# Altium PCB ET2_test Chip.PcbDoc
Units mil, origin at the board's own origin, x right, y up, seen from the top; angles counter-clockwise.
Board outline 4000 x 3600 mil, 4 copper layers (Top Layer, GND, POWER, Bottom Layer), stack 61.6 mil thick; 148 components, 68 nets, 450 pads, 320 vias.
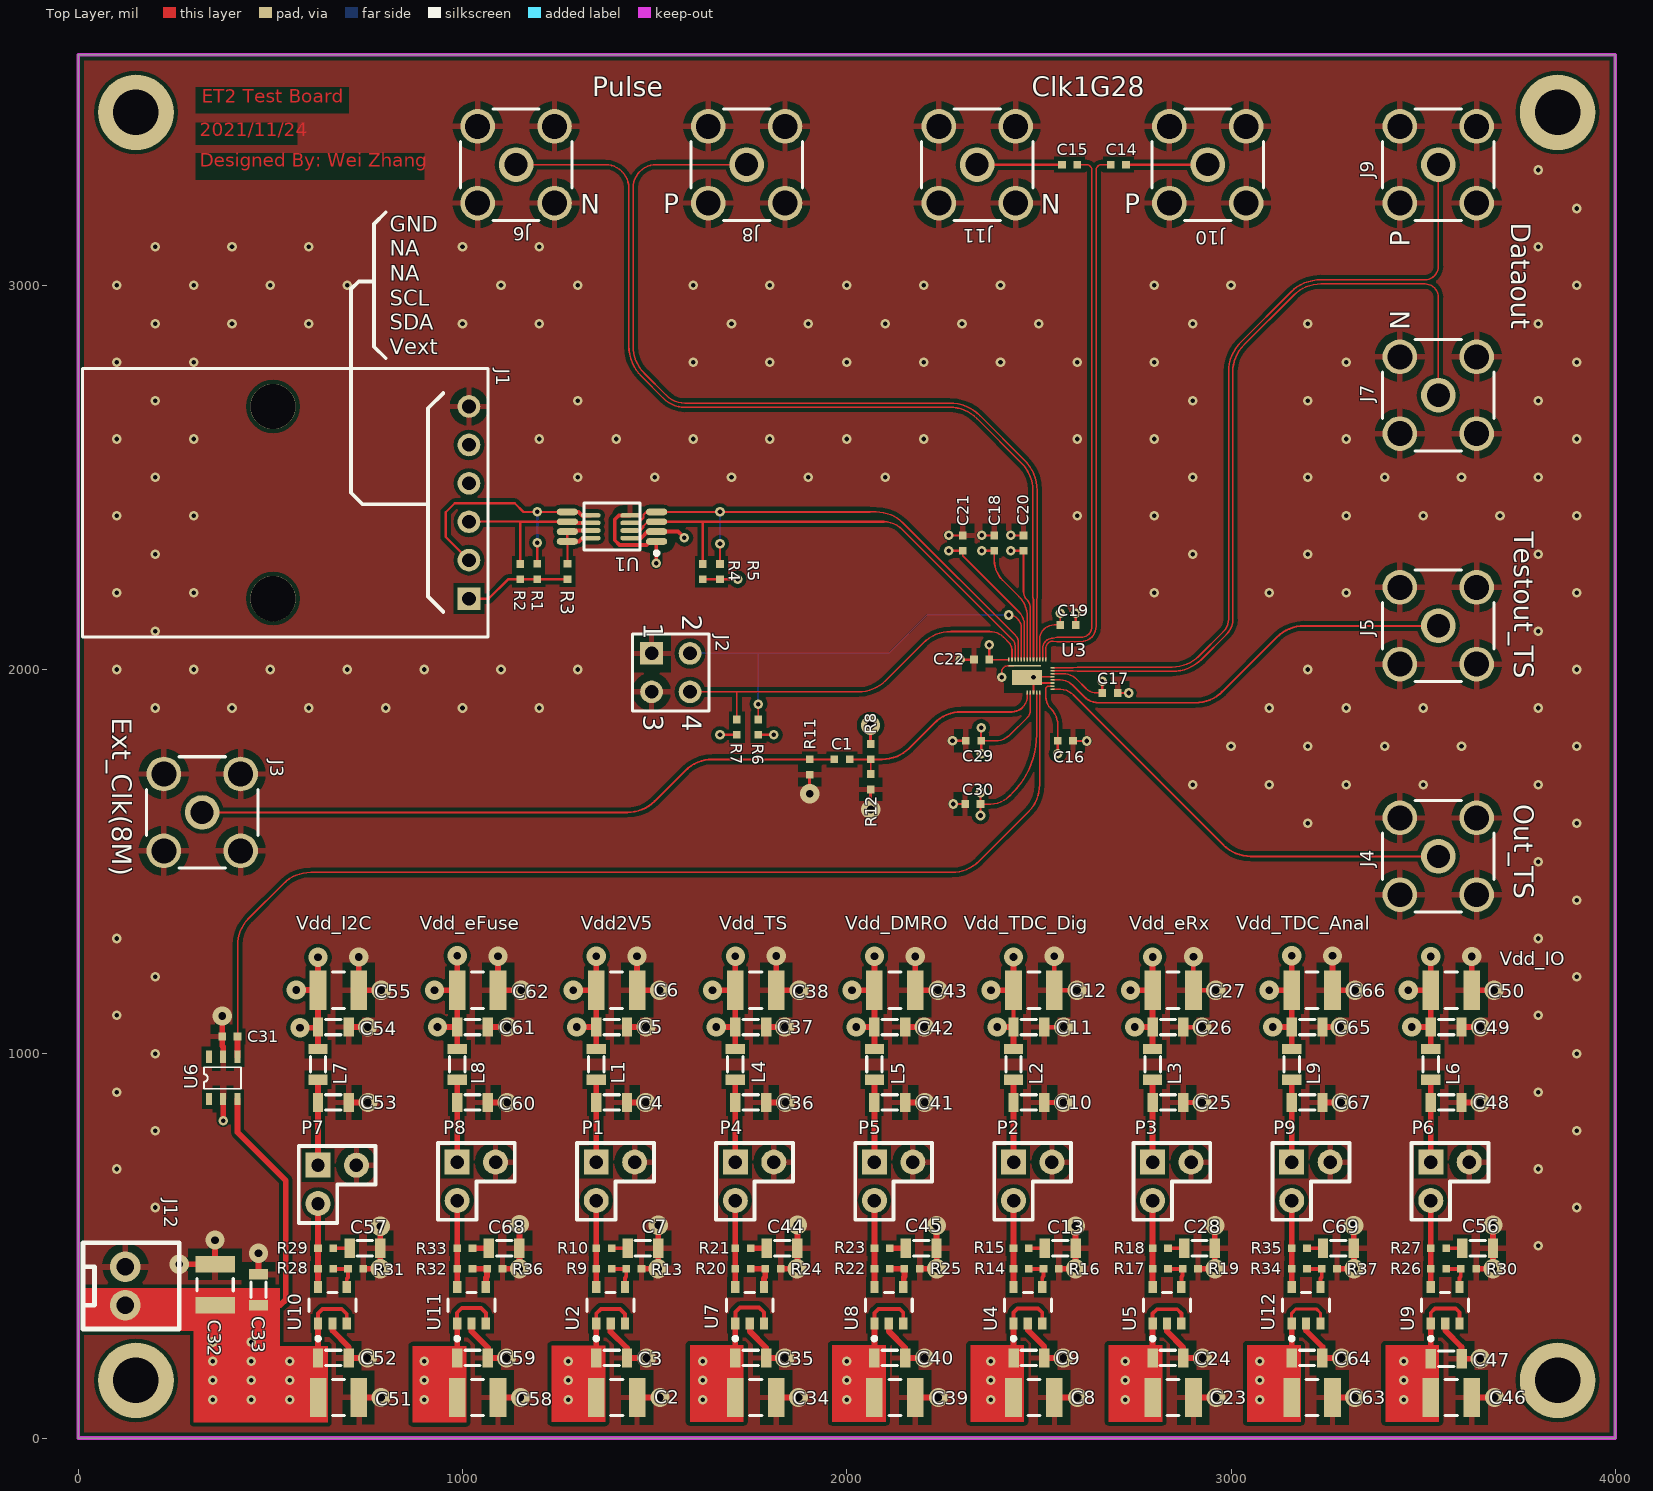
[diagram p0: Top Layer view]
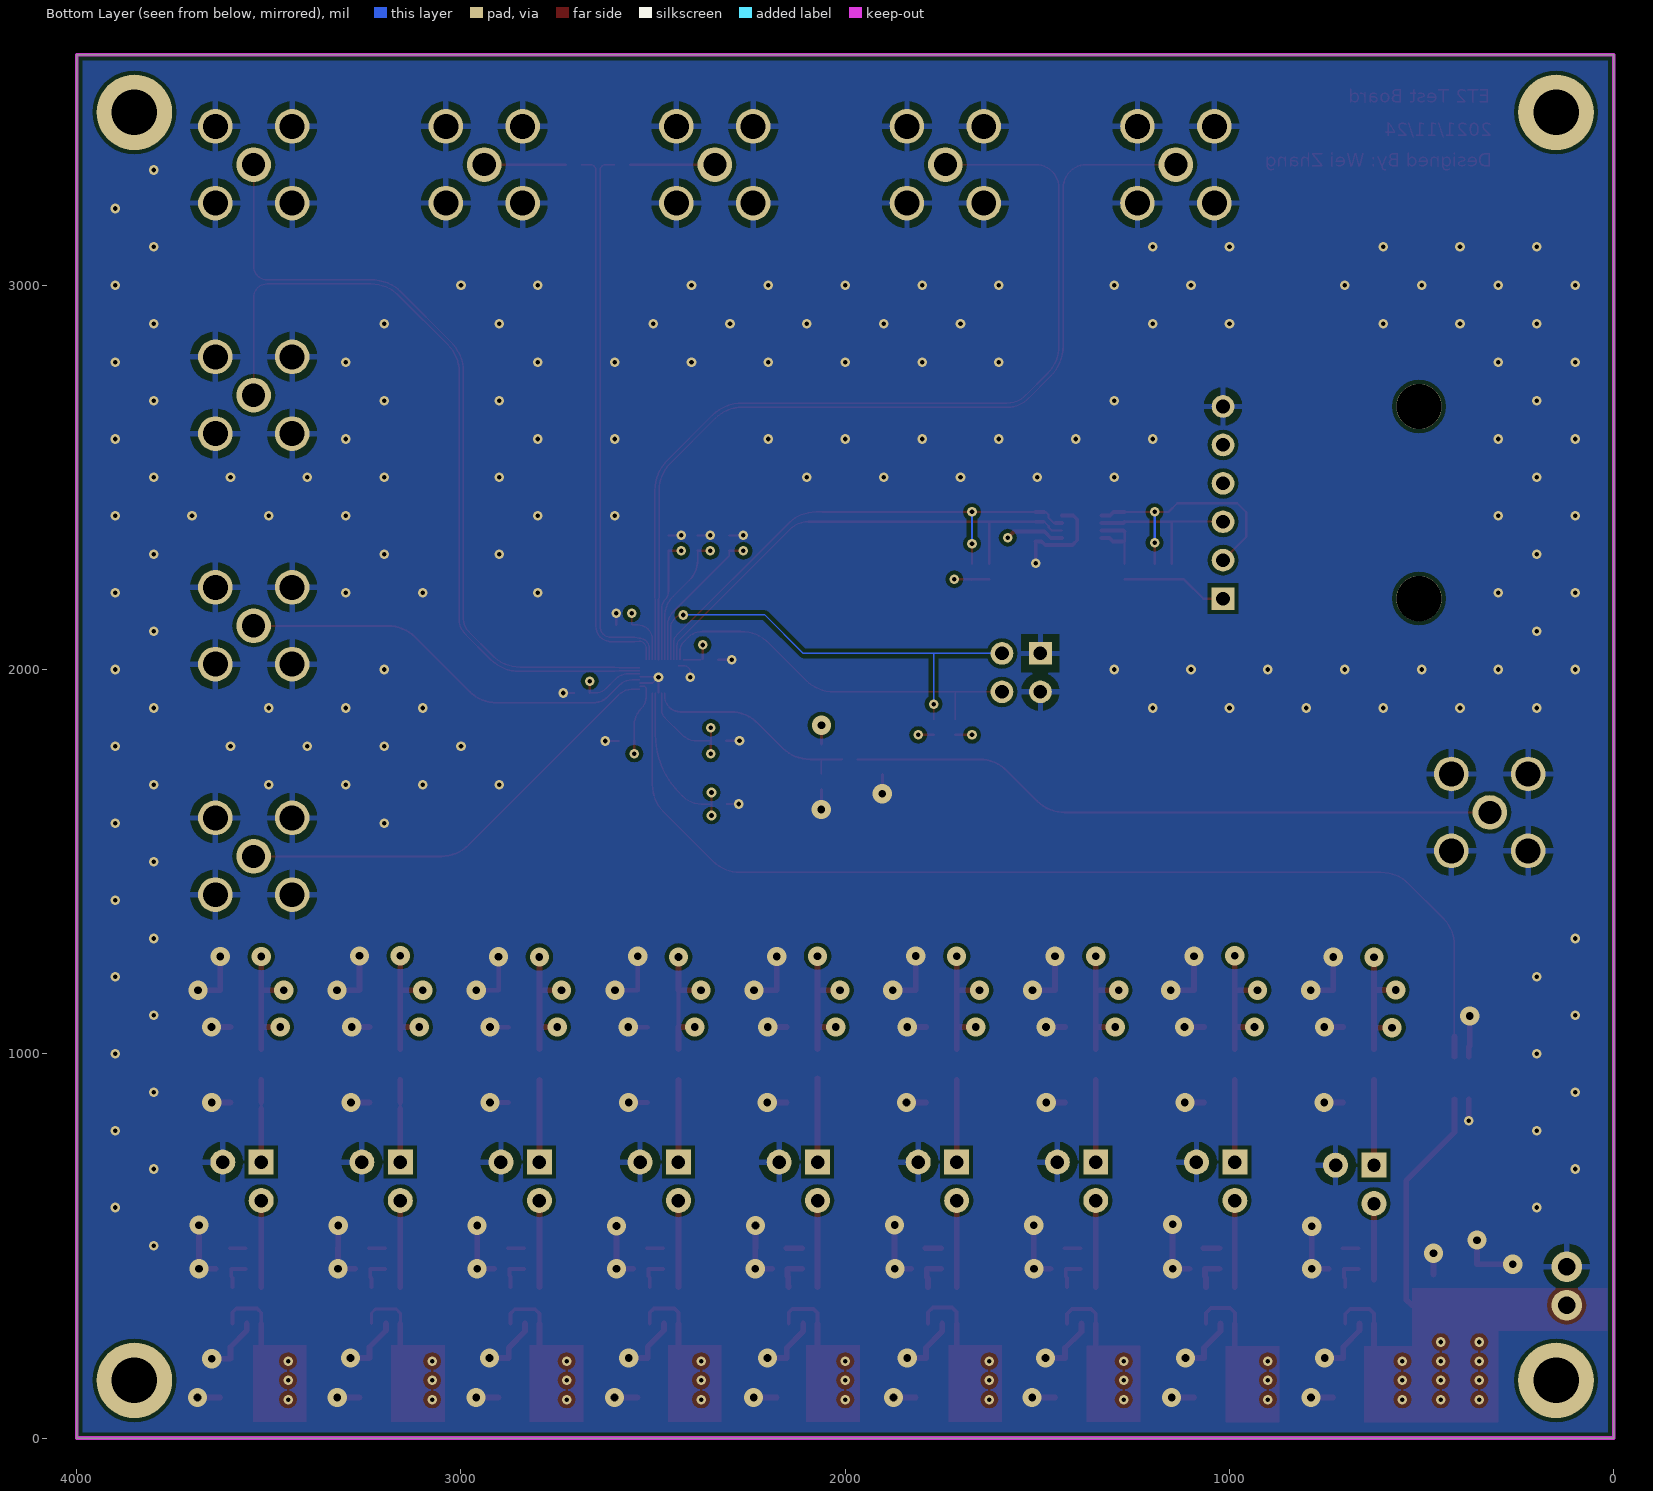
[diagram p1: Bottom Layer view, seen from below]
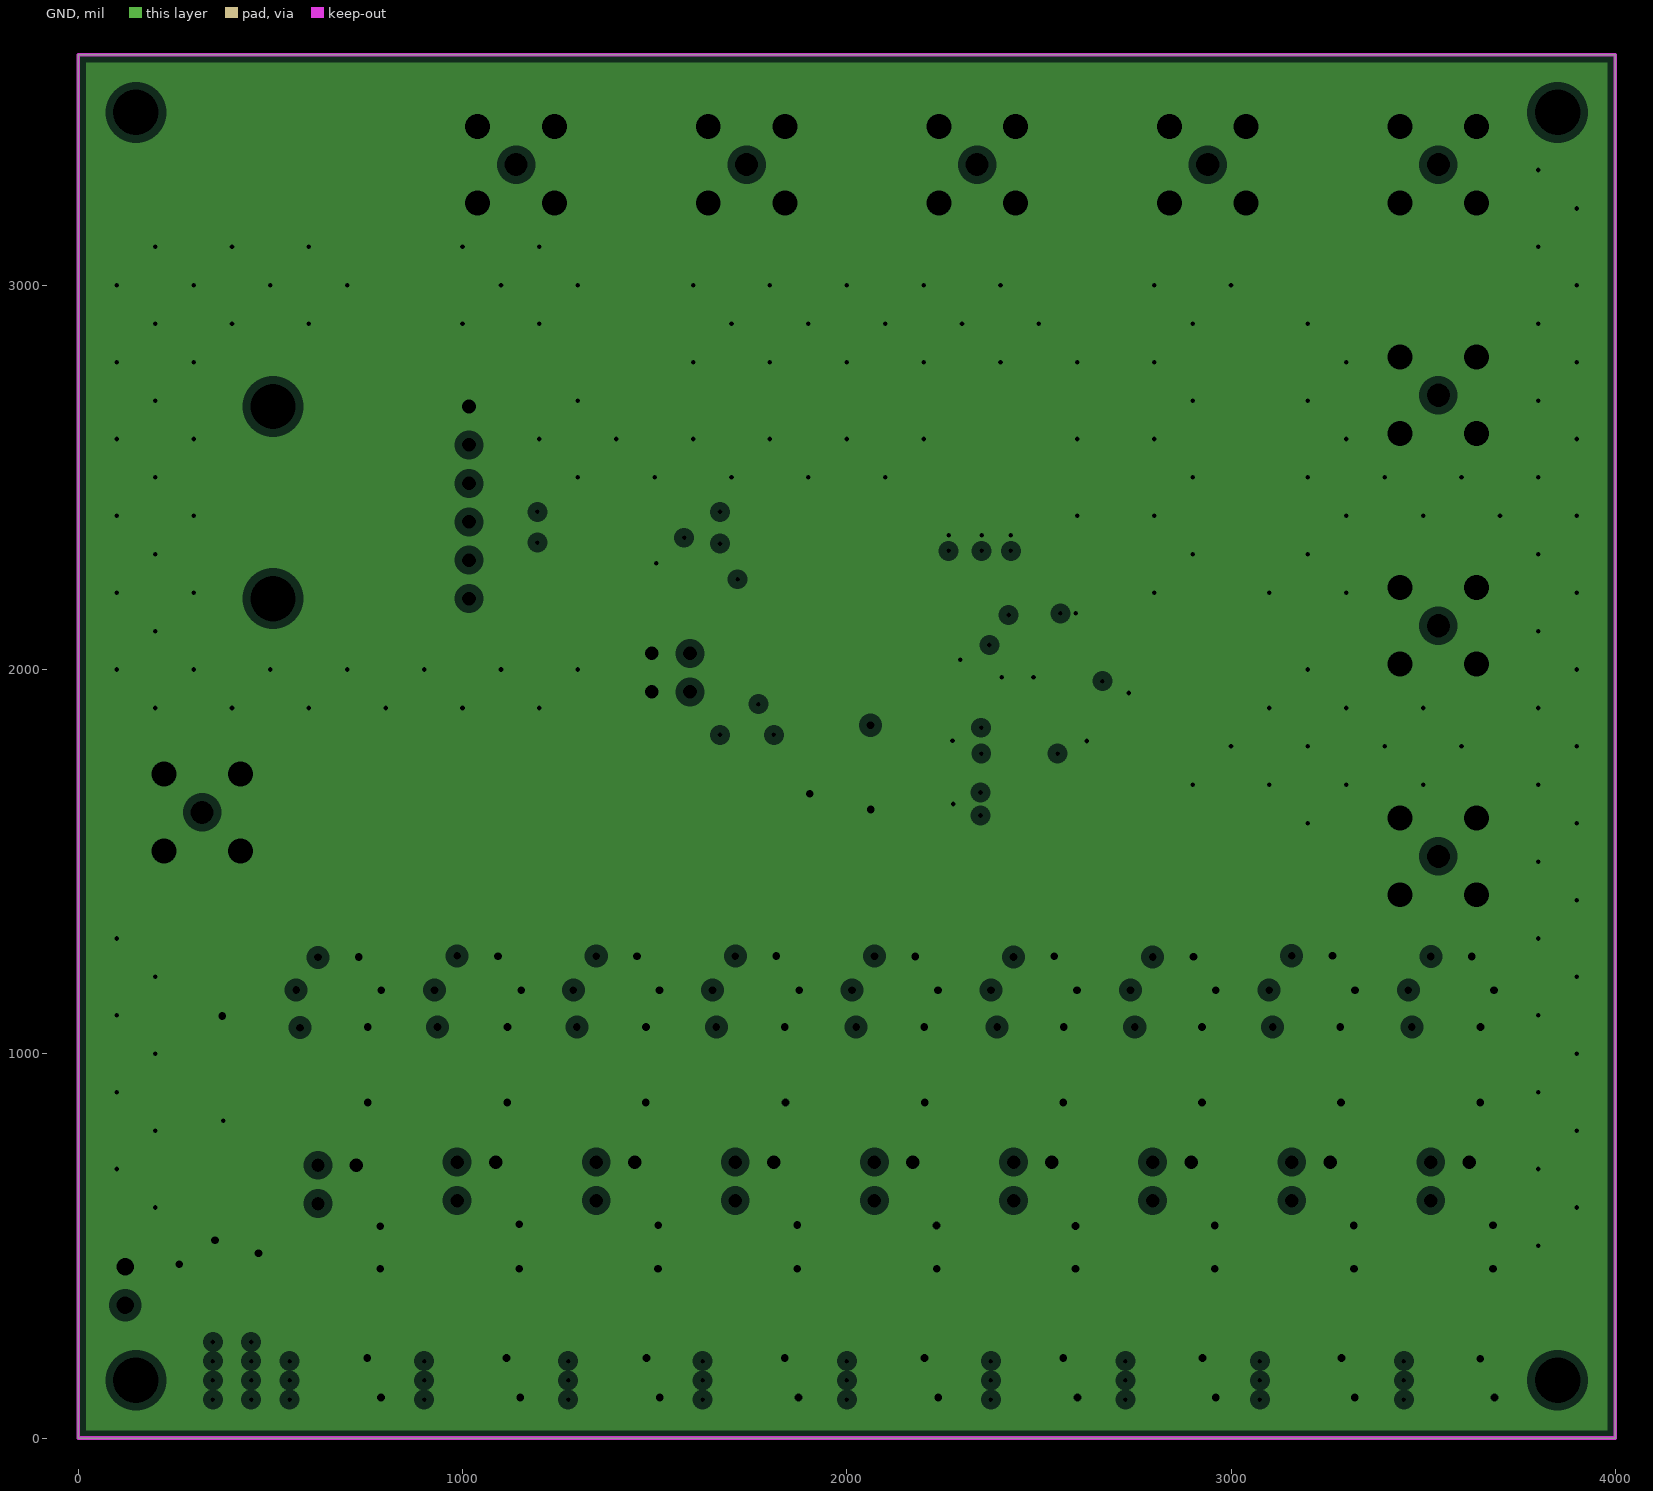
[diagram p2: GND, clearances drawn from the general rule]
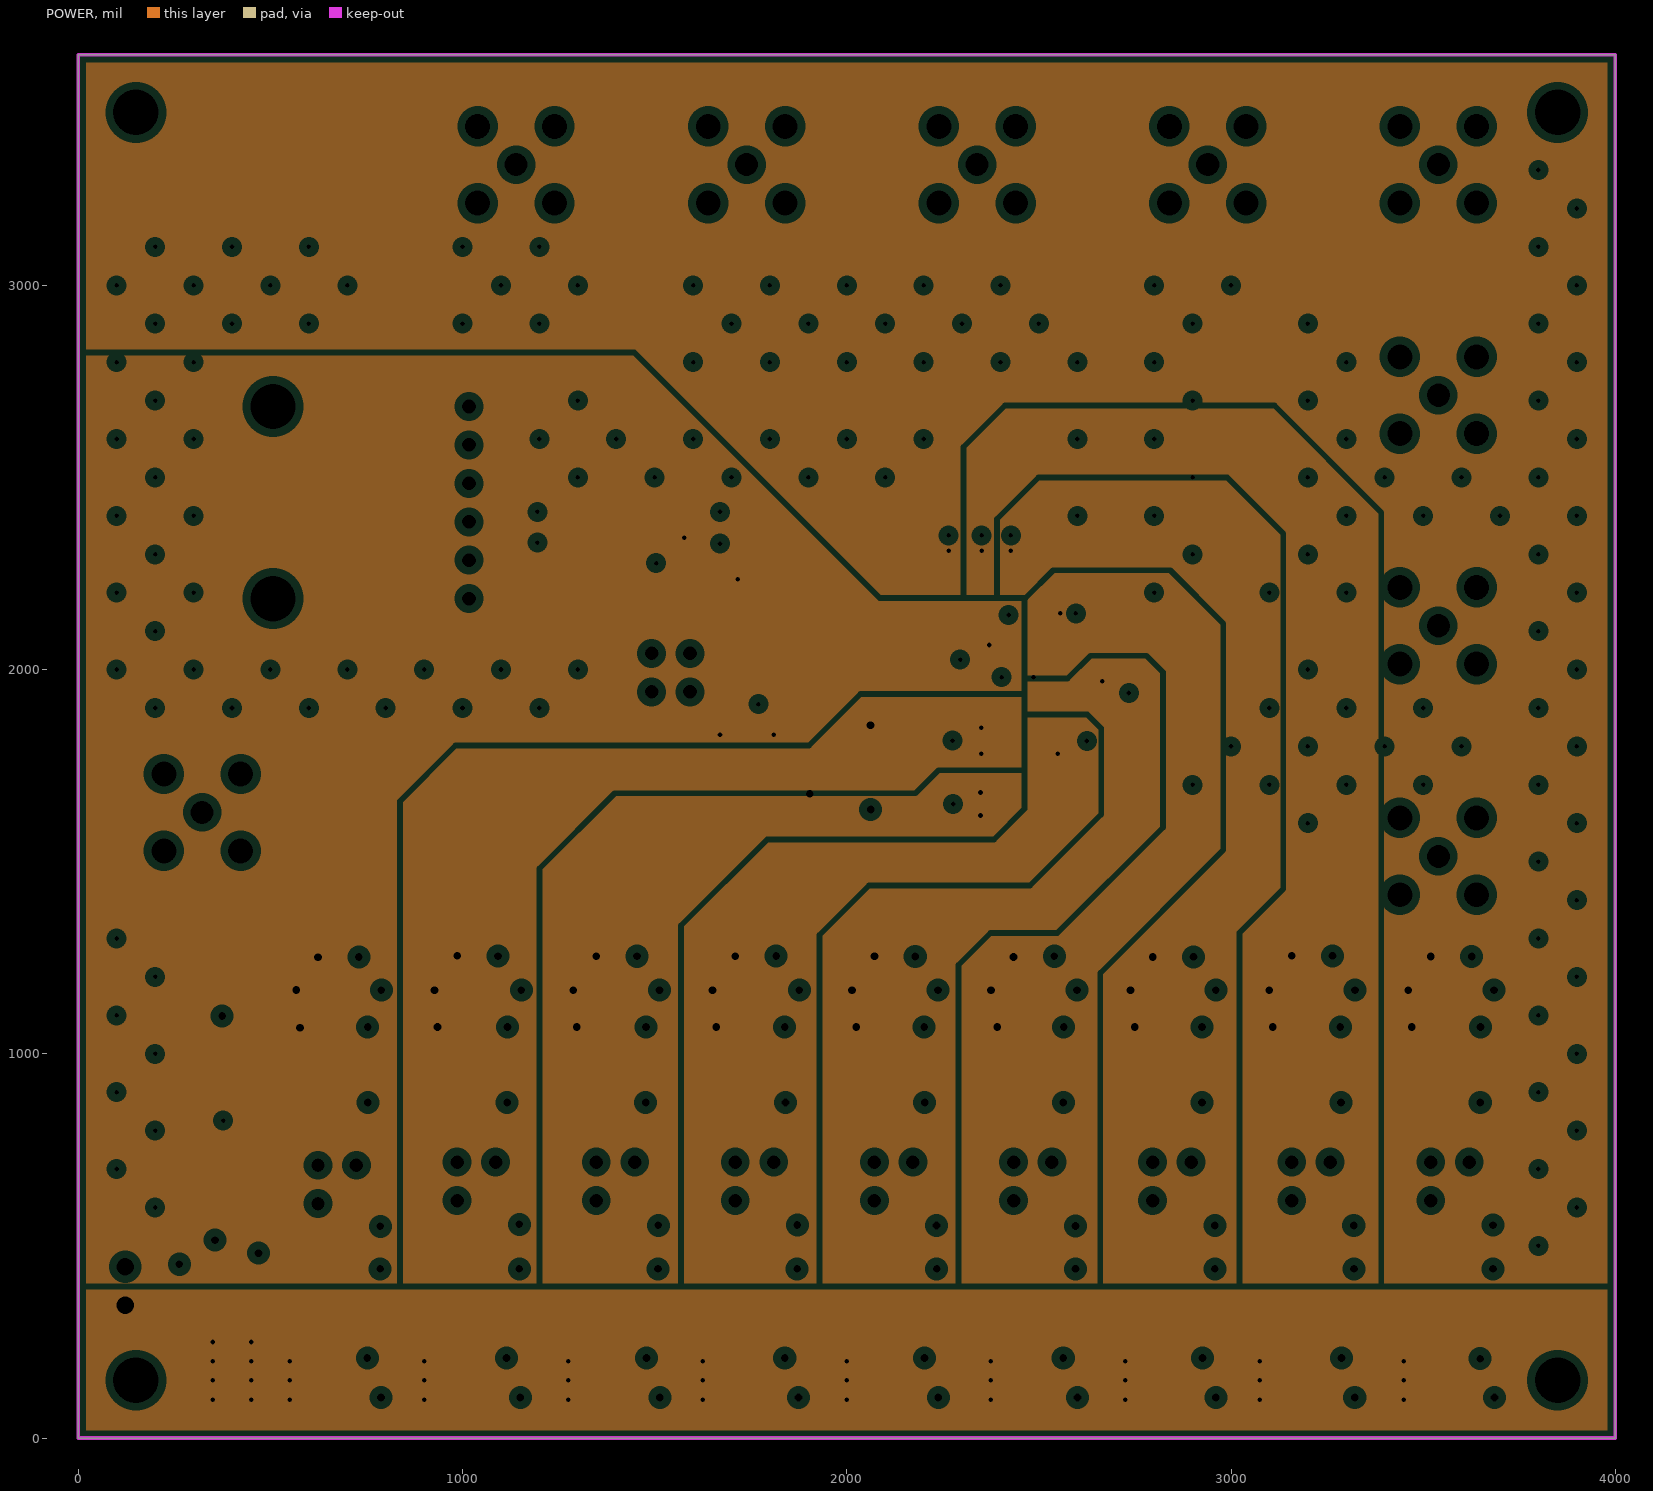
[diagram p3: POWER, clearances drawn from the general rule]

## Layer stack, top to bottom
Top Solder: solder mask 0.7, Solder Resist, Dk 3.5
Top Layer: signal copper 1.4
Dielectric 1: core 3.1, FR-4, Dk 4.2
GND: plane copper 1.3, net (Multiple Nets)
Dielectric 3: prepreg 50, Dk 4.2
POWER: plane copper 1.3, net GND
Dielectric 2: core 3.1, Dk 4.2
Bottom Layer: signal copper 1.4
Bottom Solder: solder mask 0.7, Solder Resist, Dk 3.5

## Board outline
0,0 4000,0 4000,3600 0,3600 0,0

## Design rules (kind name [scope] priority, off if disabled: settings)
Clearance [All] p1: gap=10 except(3: Track-Track Track-SMDPad SMDPad-SMDPad; 4: Arc-Arc Arc-Track Arc-SMDPad Track-THPad Track-Via SMDPad-THPad SMDPad-Via SMDPad-Region THPad-Via Text-Text)
DiffPairsRouting [All] p1: maxlimit=10 minlimit=4 mostfreqgap=7 toplayer_minwidth=4 toplayer_maxwidth=15 toplayer_prefwidth=4 bottomlayer_minwidth=4 bottomlayer_maxwidth=15 bottomlayer_prefwidth=4 maxuncoupledlength=500
PlaneClearance [All] p1: clearance=20
PlaneConnect [InNetClass('All Nets')] p1: planeconnectstyle=Relief reliefexpansion=15 reliefentries=4 reliefconductorwidth=10 reliefairgap=8
PolygonConnect PolygonConnect_1 [IsVia] p1: connectstyle=Direct reliefconductorwidth=10 reliefentries=4 polygonreliefangle="90 Angle" airgapwidth=10
PolygonConnect Via [All] p2: connectstyle=Relief reliefconductorwidth=15 reliefentries=4 polygonreliefangle="90 Angle" airgapwidth=20
RoutingVias [All] p1: holewidth=28 width=50 viastyle="Through Hole" minholewidth=28 minwidth=50 maxholewidth=28 maxwidth=50
SolderMaskExpansion [All] p1: expansion=4
Width [All] p1: maxlimit=30 minlimit=3 preferedwidth=4
27 further rules are at their usual default settings.

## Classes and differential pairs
component class ET2_test_Chip: C1 C2 C3 C4 C5 C6 C7 C8 C9 C10 C11 C12 C13 C14 C15 C16 C17 C18 C19 C20 C21 C22 C23 C24 C25 C26 C27 C28 C29 C30 J1 J2 J3 J4 J5 J6 J7 J8 J9 J10 J11 L1 L2 L3 P1 P2 P3 R1 R2 R3 R4 R5 R6 R7 R8 R9 R10 R11 R12 R13 R14 R15 R16 R17 R18 R19 U1 U2 U3 U4 U5
component class "ET2_test Chip_V1": 30 C31 C32 C33 C34 C35 C36 C37 C38 C39 C40 C41 C42 C43 C44 C45 C46 C47 C48 C49 C50 C51 C52 C53 C54 C55 C56 C57 C58 C59 C60 C61 C62 C63 C64 C65 C66 C67 C68 C69 J12 L4 L5 L6 L7 L8 L9 P4 P5 P6 P7 P8 P9 R20 R21 R22 R23 R24 R25 R26 R27 R28 R29 R30 R31 R32 R33 R34 R35 R36 R37 U6 U7 U8 U9 U10 U11 U12
differential pair CLK1G28_IN: +CLK1G28_IN_P -CLK1G28_IN_N
differential pair DATAOUT: +DATAOUT_P -DATAOUT_N
differential pair PULSE_IN: +PULSE_IN_P -PULSE_IN_N

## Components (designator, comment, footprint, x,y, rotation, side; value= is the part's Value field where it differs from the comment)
C1 "Cap" 0402-EAGLE 1967.6,1766.3 r0 top
C2 "Cap" C1210 1401.2,105.4 r180 top
C3 "Cap" 0805-EAGLE 1428,208.4 r180 top
C4 "Cap" 0805-EAGLE 1428,873.3 r180 top
C5 "Cap" 0805-EAGLE 1428,1069.5 r180 top
C6 "Cap" C1210 1401.1,1165.6 r180 top
C7 "Cap" 0805-EAGLE 1509.51,494 r180 top
C8 "Cap" C1210 2487.2,105.4 r180 top
C9 "Cap" 0805-EAGLE 2514.1,208.4 r180 top
C10 "Cap" 0805-EAGLE 2514,873.3 r180 top
C11 "Cap" 0805-EAGLE 2514,1069.5 r180 top
C12 "Cap" C1210 2487.1,1165.6 r180 top
C13 "Cap" 0805-EAGLE 2595.51,494 r180 top
C14 "Cap" 0402-EAGLE 2726.9,3314 r180 top
C15 "Cap" 0402-EAGLE 2560,3314 r0 top
C16 "Cap" 0402-EAGLE 2589,1814.3 r180 top
C17 "Cap" 0402-EAGLE 2705,1939 r180 top
C18 "Cap" 0402-EAGLE 2384,2349 r270 top
C19 "Cap" 0402-EAGLE 2596,2116 r180 top
C20 "Cap" 0402-EAGLE 2460,2349 r270 top
C21 "Cap" 0402-EAGLE 2302,2349 r270 top
C22 "Cap" 0402-EAGLE 2331,2026 r0 top
C23 "Cap" C1210 2849.1,105.4 r180 top
C24 "Cap" 0805-EAGLE 2875.9,208.4 r180 top
C25 "Cap" 0805-EAGLE 2876,873.3 r180 top
C26 "Cap" 0805-EAGLE 2876,1069.5 r180 top
C27 "Cap" C1210 2849.1,1165.6 r180 top
C28 "Cap" 0805-EAGLE 2958,494 r180 top
C29 "Cap" 0402-EAGLE 2310,1814.3 r0 top
C30 "Cap" 0402-EAGLE 2308,1650 r0 top
C31 "Cap" 0402-EAGLE 374.4,1045 r0 top
C32 "Cap" C1210 356,399 r270 top
C33 "Cap" 0805-EAGLE 469,425.8 r270 top
C34 "Cap" C1210 1763.2,105.4 r180 top
C35 "Cap" 0805-EAGLE 1790,208.4 r180 top
C36 "Cap" 0805-EAGLE 1790,873.3 r180 top
C37 "Cap" 0805-EAGLE 1790,1069.5 r180 top
C38 "Cap" C1210 1763.2,1165.6 r180 top
C39 "Cap" C1210 2125.1,105.4 r180 top
C40 "Cap" 0805-EAGLE 2151.9,208.4 r180 top
C41 "Cap" 0805-EAGLE 2152,873.3 r180 top
C42 "Cap" 0805-EAGLE 2152,1069.5 r180 top
C43 "Cap" C1210 2125.1,1165.6 r180 top
C44 "Cap" 0805-EAGLE 1871.51,494 r180 top
C45 "Cap" 0805-EAGLE 2233.51,494 r180 top
C46 "Cap" C1210 3573.3,105.4 r180 top
C47 "Cap" 0805-EAGLE 3600.2,206.4 r180 top
C48 "Cap" 0805-EAGLE 3600,873.3 r180 top
C49 "Cap" 0805-EAGLE 3600,1069.5 r180 top
C50 "Cap" C1210 3573.2,1165.6 r180 top
C51 "Cap" C1210 677.2,105.4 r180 top
C52 "Cap" 0805-EAGLE 703.9,208.4 r180 top
C53 "Cap" 0805-EAGLE 703.9,873.3 r180 top
C54 "Cap" 0805-EAGLE 703.9,1069.5 r180 top
C55 "Cap" C1210 677,1165.6 r180 top
C56 "Cap" 0805-EAGLE 3682,494 r180 top
C57 "Cap" 0805-EAGLE 786,494 r180 top
C58 "Cap" C1210 1039.1,105.4 r180 top
C59 "Cap" 0805-EAGLE 1066,208.4 r180 top
C60 "Cap" 0805-EAGLE 1066,873.3 r180 top
C61 "Cap" 0805-EAGLE 1066,1069.5 r180 top
C62 "Cap" C1210 1039.2,1165.6 r180 top
C63 "Cap" C1210 3211.1,105.4 r180 top
C64 "Cap" 0805-EAGLE 3237.8,208.4 r180 top
C65 "Cap" 0805-EAGLE 3238,1069.5 r180 top
C66 "Cap" C1210 3211.1,1165.6 r180 top
C67 "Cap" 0805-EAGLE 3238,873.3 r180 top
C68 "Cap" 0805-EAGLE 1148,494 r180 top
C69 "Cap" 0805-EAGLE 3319.51,494 r180 top
J1 "Header 6" USB_ISS 1016.8,2184.6 r90 top
J2 "Header 2X2" HDR2X2 1492,2042 r270 top
J3 "SMA1" SMA_MID 322.5,1628.1 r0 top
J4 "SMA1" SMA_MID 3539.5,1513.9 r0 top
J5 "SMA1" SMA_MID 3539.5,2113.9 r0 top
J6 "SMA1" SMA_MID 1139.5,3313.9 r0 top
J7 "SMA1" SMA_MID 3539.5,2713.9 r0 top
J8 "SMA1" SMA_MID 1739.5,3313.9 r0 top
J9 "SMA1" SMA_MID 3539.5,3313.9 r0 top
J10 "SMA1" SMA_MID 2939.5,3313.9 r0 top
J11 "SMA1" SMA_MID 2339.5,3313.9 r0 top
J12 "Header 2" POWERJ2 122.3,345.7 r180 top
L1 "Inductor" 0805-EAGLE 1348,932.3 r90 top
L2 "Inductor" 0805-EAGLE 2434,932.3 r90 top
L3 "Inductor" 0805-EAGLE 2796,932.3 r90 top
L4 "Inductor" 0805-EAGLE 1710,932.3 r90 top
L5 "Inductor" 0805-EAGLE 2072,932.3 r90 top
L6 "Inductor" 0805-EAGLE 3520,932.3 r90 top
L7 "Inductor" 0805-EAGLE 623.9,932.3 r90 top
L8 "Inductor" 0805-EAGLE 986,932.3 r90 top
L9 "Inductor" 0805-EAGLE 3158,932.3 r90 top
P1 "Header 3" HEADER3_L 1348,718 r270 top
P2 "Header 3" HEADER3_L 2434,718 r270 top
P3 "Header 3" HEADER3_L 2796,718 r270 top
P4 "Header 3" HEADER3_L 1710,718 r270 top
P5 "Header 3" HEADER3_L 2072,718 r270 top
P6 "Header 3" HEADER3_L 3520,718 r270 top
P7 "Header 3" HEADER3_L 623.9,710 r270 top
P8 "Header 3" HEADER3_L 986,718 r270 top
P9 "Header 3" HEADER3_L 3158,718 r270 top
R1 "Res1" 0402-EAGLE 1194.8,2275 r270 top
R2 "Res1" 0402-EAGLE 1150,2274.6 r270 top
R3 "Res1" 0402-EAGLE 1273,2275 r270 top
R4 "Res1" 0402-EAGLE 1625.3,2274.6 r270 top
R5 "Res1" 0402-EAGLE 1670,2274.6 r270 top
R6 "Res1" 0402-EAGLE 1770,1869.9 r270 top
R7 "Res1" 0402-EAGLE 1714,1869.9 r270 top
R8 "Res1" 0402-EAGLE 2062.2,1766.41 r90 top
R9 "1%" 0402-EAGLE 1388,440.28 r180 top
R10 "1%" 0402-EAGLE 1388,494 r180 top
R11 "Res1" 0402-EAGLE 1903.5,1726.4 r90 top
R12 "Res1" 0402-EAGLE 2062.2,1688 r90 top
R13 "1%" 0402-EAGLE 1466.01,440.28 r180 top
R14 "1%" 0402-EAGLE 2474,440.28 r180 top
R15 "1%" 0402-EAGLE 2474,494 r180 top
R16 "1%" 0402-EAGLE 2552.01,440.28 r180 top
R17 "1%" 0402-EAGLE 2836,440.28 r180 top
R18 "1%" 0402-EAGLE 2836,494 r180 top
R19 "1%" 0402-EAGLE 2914.01,440.28 r180 top
R20 "1%" 0402-EAGLE 1750,440.28 r180 top
R21 "1%" 0402-EAGLE 1750,494 r180 top
R22 "1%" 0402-EAGLE 2112,440.28 r180 top
R23 "1%" 0402-EAGLE 2112,494 r180 top
R24 "1%" 0402-EAGLE 1828.01,440.28 r180 top
R25 "1%" 0402-EAGLE 2190.01,440.28 r180 top
R26 "1%" 0402-EAGLE 3560,440.28 r180 top
R27 "1%" 0402-EAGLE 3560,494 r180 top
R28 "1%" 0402-EAGLE 663.9,440.28 r180 top
R29 "1%" 0402-EAGLE 663.9,494 r180 top
R30 "1%" 0402-EAGLE 3638.01,440.28 r180 top
R31 "1%" 0402-EAGLE 741.91,440.28 r180 top
R32 "1%" 0402-EAGLE 1026,440.28 r180 top
R33 "1%" 0402-EAGLE 1026,494 r180 top
R34 "1%" 0402-EAGLE 3198,440.28 r180 top
R35 "1%" 0402-EAGLE 3198,494 r180 top
R36 "1%" 0402-EAGLE 1104.01,440.28 r180 top
R37 "1%" 0402-EAGLE 3276.01,440.28 r180 top
U1 "PCA9306DCUR" PCA9306 1384.9,2371.7 r180 top
U2 "AP7331-WG-7" FP-SOT25-MFG 1385.4,345.4 r90 top
U3 "ET2_test Chip" "ET2_TEST CHIP" 2430,1960 r0 top
U4 "AP7331-WG-7" FP-SOT25-MFG 2471.4,345.4 r90 top
U5 "AP7331-WG-7" FP-SOT25-MFG 2833.4,345.4 r90 top
U6 "ADR130AUJZ" ADR130 377,937 r90 top
U7 "AP7331-WG-7" FP-SOT25-MFG 1747.4,345.4 r90 top
U8 "AP7331-WG-7" FP-SOT25-MFG 2109.4,345.4 r90 top
U9 "AP7331-WG-7" FP-SOT25-MFG 3557.4,345.4 r90 top
U10 "AP7331-WG-7" FP-SOT25-MFG 661.4,345.4 r90 top
U11 "AP7331-WG-7" FP-SOT25-MFG 1023.4,345.4 r90 top
U12 "AP7331-WG-7" FP-SOT25-MFG 3195.4,345.4 r90 top

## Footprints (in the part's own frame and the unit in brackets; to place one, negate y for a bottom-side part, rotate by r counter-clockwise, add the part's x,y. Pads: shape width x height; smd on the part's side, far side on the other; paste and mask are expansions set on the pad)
0402-EAGLE [mil]
  rect 20x20 smd: 1(0,0) 2(40,0)
0805-EAGLE [mil]
  rect 27x50 smd: 1(0,0) 2(80,0)
  silkscreen extent 20,-20 60,20
ADR130 [mm]
  rect 0.8x0.4 smd: 1(-1.4,0.95) 2(-1.4,0) 3(-1.4,-0.95) 4(1.4,-0.95) 5(1.4,0) 6(1.4,0.95)
  silkscreen extent -0.71,-1.17 0.71,1.27
C1210 [mm] "Chip Capacitor, Body 3.2x2.5mm, IPC High Density"
  rect 1.1x2.6 smd: 1(-1.35,0) 2(1.35,0)
  silkscreen extent -0.4,-1.2 0.4,1.2, body extent -1.7,-1.35 1.7,1.35, height 1.3
"ET2_TEST CHIP" [mil]
  rect 2.56x2.56 on Mech13: 0(5.12,36.8) 0(8.66,36.8) 0(12.4,36.8) 0(16.73,36.8) 0(21.06,36.8) 0(25.4,36.8) 0(29.14,36.8) 0(32.68,36.8) 0(36.2,36.8) 0(40.53,36.8) 0(43.76,36.8) 0(46.03,2.57) 0(48.19,36.8) 0(49.13,2.57) 0(51.37,36.8) 0(52.13,2.57) 0(55.71,36.8) 0(59.52,36.8) 0(62.94,2.57) 0(63.07,36.8) 0(66.89,36.77) 0(69.92,2.57) 0(71.22,36.8) 0(76.17,5.18) 0(76.17,9.11) 0(76.17,12.11) 0(76.17,16.05) 0(76.17,19.89) 0(76.17,22.89) 0(76.17,26.07) 0(76.17,30.01)
  rect 78.74x39.37 smd paste-100: 0(39.37,19.68)
  rect 4x10 smd paste-10: 1(40,-20) 2(48,-20) 3(56,-20) 4(64,-20) 5(72,-20) 14(88,66) 15(80,66) 16(72,66) 18(64,66) 19(56,66) 20(48,66) 22(40,66) 25(32,66) 26(24,66) 27(16,66) 28(8,66) 29(0,66) 30(-8,66)
  rect 10x4 smd paste-10: 6(105,-11) 7(105,-3) 8(105,5) 9(105,13) 10(105,21) 11(105,29) 12(105,37) 13(105,45)
  rect 15x4 smd paste-10: 17(68,50) 21(53,50) 23(39,50) 24(24,50)
  rect 25x4 smd paste-10: 31(4,50)
FP-SOT25-MFG [mm]
  rect 0.8x0.55 smd paste+0: 1(-1.2,0.95) 2(-1.2,0) 3(-1.2,-0.95) 4(1.2,-0.95) 5(1.2,0.95)
  silkscreen extent -2.32,-1.55 0.85,1.55, body extent -1.7,-1.65 1.7,1.65, height 0.25
HDR2X2 [mm] "Connector; Header; 2x2 Position"
  rect 1.5x1.5 hole 0.9: 1(0,0)
  round 1.5 hole 0.9: 2(0,2.54) 3(2.54,0) 4(2.54,2.54)
  silkscreen extent -1.27,-1.27 3.81,3.81
HEADER3_L [mil]
  round 65 / inner oval 65x64 / far side round 65 hole 35: 1(100,0) 3(0,100)
  rect 65x65 / inner rect 65x64 / far side rect 65x65 hole 35: 2(0,0)
  silkscreen extent -50,-50 150,150
PCA9306 [mm] "PCA9306DTR2G(TSSOP8)+PCA9306DC(VSSOP8)"
  oval 1.4x0.45 smd: 1(-3.052,0.972) 2(-3.052,0.322) 3(-3.052,-0.328) 4(-3.052,-0.978) 5(2.848,-0.978) 6(2.848,-0.328) 7(2.848,0.322) 8(2.848,0.972)
  oval 1.3x0.3 smd: 1(-1.3,-0.75) 2(-1.3,0.75) 3(-1.3,0.25) 4(-1.3,-0.25) 5(1.3,-0.75) 6(1.3,-0.25) 7(1.3,0.25) 8(1.3,0.75)
  Top Layer lines w0.152: -1.3,0.25 -1.972,0.25 -2.169,0.053 -2.169,-0.033 -2.464,-0.328 -2.56,-0.328 -3.052,-0.328 ; -1.3,-0.25 -1.741,-0.25 -1.844,-0.25 -2.192,-0.598 -2.192,-0.785 -2.385,-0.978 -3.052,-0.978
  Top Layer lines w0.254: 2.848,-0.328 2.771,-0.25 1.3,-0.25 ; 2.848,-0.978 2.103,-0.978 1.875,-0.75 1.3,-0.75 ; 2.817,0.998 2.791,0.972 2.07,0.972 1.847,0.75 1.3,0.75 ; 1.3,0.25 2.776,0.25 2.848,0.322 ; -1.3,0.75 -2.034,0.75 -2.461,0.322 -3.052,0.322 ; -1.3,-0.25 -1.741,-0.25 ; -1.3,-0.75 -0.554,-0.75 -0.287,-0.483 -0.287,0.897 -0.605,1.214 -2.398,1.214 -2.639,0.972 -3.052,0.972 ; -2.469,-0.978 -3.052,-0.978 ; -2.56,-0.328 -3.052,-0.328 ; 2.848,0.322 2.848,0.322
  silkscreen extent -3.18,-1.55 1.75,1.87
POWERJ2 [mil]
  round 80 hole 45: 1(0,0) 2(0,-100)
  silkscreen extent -140,-162 110,62
SMA_MID [mil]
  round 90 hole 60: 1(0,0)
  round 90 hole 65: 2(-100,100) 3(-100,-100) 4(100,-100) 5(100,100)
  silkscreen extent -145,-145 145,145
USB_ISS [mm] "USB-ISS modul for I2C, SPI, serial port"
  rect 1.5x1.5 hole 0.9: 1(0,0)
  round 1.5 hole 0.9: 2(2.54,0) 3(5.08,0) 4(7.62,0) 5(10.16,0) 6(12.7,0)
  round 3 hole 3 unplated: ""(0,12.954) ""(12.7,12.954)
  silkscreen extent -2.54,-1.27 15.21,25.54

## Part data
C1 C2 C3 C4 C5 C6 C7 C8 C9 C10 C11 C12 C13 C14 C15 C16 C17 C18 C19 C20 C21 C22 C23 C24 C25 C26 C27 C28 C29 C30 C31 C32 C33 C34 C35 C36 C37 C38 C39 C40 C41 C42 C43 C44 C45 C46 C47 C48 C49 C50 C51 C52 C53 C54 C55 C56 C57 C58 C59 C60 C61 C62 C63 C64 C65 C66 C67 C68 C69: "Capacitor"
J1: "Header, 6-Pin"
J2: "Header, 2-Pin, Dual row"
J12: "Header, 2-Pin"
P1 P2 P3 P4 P5 P6 P7 P8 P9: "Header, 3-Pin"
R1 R2 R3 R4 R5 R6 R7 R8 R11 R12: "Resistor"
R9 R10 R13 R14 R15 R16 R17 R18 R19 R20 R21 R22 R23 R24 R25 R26 R27 R28 R29 R30 R31 R32 R33 R34 R35 R36 R37: library part Res1, "Resistor"
U1: library part PCA9306
U2 U4 U5 U7 U8 U9 U10 U11 U12: library part CMP-12756-000022-1, "IC REG LIN POS ADJ 300MA SOT25"
U6: library part ADR130

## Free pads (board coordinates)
  round 196.85 hole 118.11: 0(150,150) 0(150,3450) 0(3850,150) 0(3850,3450)

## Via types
v1: diameter 25, hole 12, Top Layer to Bottom Layer, tented both sides, 214 vias
v2: diameter 50, hole 20, Top Layer to Bottom Layer, tented both sides, 106 vias

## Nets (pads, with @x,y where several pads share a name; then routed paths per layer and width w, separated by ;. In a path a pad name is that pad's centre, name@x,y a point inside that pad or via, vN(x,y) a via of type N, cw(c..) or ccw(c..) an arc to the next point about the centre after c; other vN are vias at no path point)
CLK1G28_IN_N: C15.2 U3.15 | length 1422.4
  Top Layer w4: U3.15 2510,2055 cw(c2537,2055) 2537,2082 2546.6,2083.5 2609.1,2083.5 ccw(c2609.1,2112.3) 2637.9,2112.3 2637.9,3299.9 ccw(c2623.8,3299.9) 2623.8,3314 C15.2
CLK1G28_IN_P: C14.2 U3.14 | length 1427.2
  Top Layer w4: U3.14 2518,2055 cw(c2537,2055) 2537,2074 2546.6,2072.5 2609.1,2072.5 ccw(c2609.1,2112.3) 2648.9,2112.3 2648.9,3299.9 cw(c2663,3299.9) 2663,3314 C14.2
DATAOUT_N: J7.1 U3.12 | length 2096
  Top Layer w4: U3.12 2589.5,1997 2599.7,1995.4 2847.44,1995.4 ccw(c2847.44,2103.36) 2923.78,2027.02 2988.01,2091.26 ccw(c2947.97,2131.3) 3004.6,2131.3 3004.6,2774.28 cw(c3104.6,2774.28) 3033.89,2844.99 3163.15,2974.25 cw(c3233.86,2903.54) 3233.86,3003.54 3504.9,3003.54 cw(c3504.9,2968.94) 3539.5,2968.94 J7.1
DATAOUT_P: J9.1 U3.13 | length 2105.7
  Top Layer w4: U3.13 2589.5,2005 2599.7,2006.4 2847.44,2006.4 ccw(c2847.44,2103.36) 2916,2034.8 2980.24,2099.04 ccw(c2947.97,2131.3) 2993.6,2131.3 2993.6,2774.28 cw(c3104.6,2774.28) 3026.11,2852.77 3155.37,2982.03 cw(c3233.86,2903.54) 3233.86,3014.54 3504.9,3014.54 ccw(c3504.9,3049.14) 3539.5,3049.14 J9.1
GND: C2.1 C3.1 C4.1 C5.1 C6.1 C7.1 C8.1 C9.1 C10.1 C11.1 C12.1 C13.1 C16.1 C17.1 C18.1 C19.1 C20.1 C21.1 C22.1 C23.1 C24.1 C25.1 C26.1 C27.1 C28.1 C29.1 C30.1 C31.1 C32.1 C33.1 C34.1 C35.1 C36.1 C37.1 C38.1 C39.1 C40.1 C41.1 C42.1 C43.1 C44.1 C45.1 C46.1 C47.1 C48.1 C49.1 C50.1 C51.1 C52.1 C53.1 C54.1 C55.1 C56.1 C57.1 C58.1 C59.1 C60.1 C61.1 C62.1 C63.1 C64.1 C65.1 C66.1 C67.1 C68.1 C69.1 J1.6 J2.1 J2.3 J3.2 J3.3 J3.4 J3.5 J4.2 J4.3 J4.4 J4.5 J5.2 J5.3 J5.4 J5.5 J6.2 J6.3 J6.4 J6.5 J7.2 J7.3 J7.4 J7.5 J8.2 J8.3 J8.4 J8.5 J9.2 J9.3 J9.4 J9.5 J10.2 J10.3 J10.4 J10.5 J11.2 J11.3 J11.4 J11.5 J12.2 P1.3 P2.3 P3.3 P4.3 P5.3 P6.3 P7.3 P8.3 P9.3 R11.1 R12.1 R13.1 R16.1 R19.1 R24.1 R25.1 R30.1 R31.1 R36.1 R37.1 U1.1 U2.2 U3.0@2469.37,1979.68 U3.3 U3.8 U3.10 U3.17 U3.21 U3.23 U3.24 U3.31 U4.2 U5.2 U6.2 U6.5 U7.2 U8.2 U9.2 U10.2 U11.2 U12.2 | length 6666.7
  Top Layer w4: v1(2403,1980) 2403,1994 cw(c2417.49,1994) 2407.23,2004.23 2408,2005 ; 2407.69,2004.7 cw(c2420.52,1991.82) 2420.52,2010 U3.31 ; U3.3 v1(2486,1980) ; U3.8 2501,1965 v1(2486,1980) ; U3.10 2487,1981 v1(2486,1980) ; C16.1 C16.1@2589.3,1814
  Top Layer w6: v1(2265,2349) C21.1 ; v1(2275.3,1814.8) C29.1@2309.5,1814.8 ; v1(2277,1650) C30.1 ; v1(2295,2025.5) 2330.5,2025.5 C22.1 ; v1(2351,2349) C18.1 ; v1(2427,2349) C20.1 ; C16.1@2589.3,1814 v1(2625,1814) ; C19.1 v1(2596,2146) ; C17.1 v1@2741,1939
  Top Layer w8: v2@1903,1676.3 v2(1903.5,1676.8) R11.1 ; v2(2062.2,1635.8) R12.1
  Top Layer w10: v1(1504,2277) 1504,2332.37 U1.1@1505.04,2333.41
  Top Layer w12: C10.1 v2(2563.7,873.3) v2@2564,873 ; C11.1 v2(2564.5,1069.5) v2@2566,1068 ; v2(2540.25,1253.75) C12.1 v2(2599.4,1165.6) ; C25.1 v2(2924.7,873.3) v2@2925,873 ; C26.1 v2(2924.5,1069.5) v2@2925,1070 ; v2@2905,1255 v2(2902.25,1252.25) C27.1 v2(2960.4,1165.6) v2@2961,1165
  Top Layer w15: v2(262.85,452.15) C32.1 v2(356,515) ; v2(374.4,1098.4) C31.1 374.4,1024.28 ccw(c383.28,1024.28) 377,1018 U6.5 ; v1(377,826) U6.2 ; C33.1 v2(469,481) ; U10.2 661.4,279.6 703.9,237.1 C52.1 v2(752.4,208.4) v2@753,209 ; C53.1 v2(753.7,873.3) v2@755,872 ; C54.1 v2(753,1069.5) ; v2(730,1252) 730,1165.75 C55.1 v2(788.6,1165.6) ; C51.1 v2(787.6,105.4) v2@788,105 ; R31.1 v2(785.72,440.28) 786,440.55 C57.1 v2(786,551) v2@786,557 ; U11.2 1023.4,277.6 1066,235 C59.1 v2(1114.4,208.4) v2@1115,209 ; C60.1 v2(1116,873.3) v2@1116,873 ; C61.1 v2(1117,1069.5) v2@1117,1072 ; v2@1089,1254 v2(1092.35,1254) C62.1 v2(1153,1165.6) ; C58.1 v2(1150.6,105.4) v2@1151,105 ; R36.1 v2(1148,440.28) C68.1 v2(1148,556) v2@1149,556 ; U2.2 1385.4,276.6 1428,234 C3.1 v2(1478.6,208.4) v2@1479,208 ; C4.1 v2(1476.7,873.3) ; C5.1 v2(1477.5,1069.5) ; v2@1454,1254 v2(1454.25,1253.75) C6.1 v2(1512.4,1165.6) ; C2.1 v2(1513.6,105.4) v2@1515,104 ; R13.1 v2(1508.72,440.28) ; v2@1509.51,441.06 C7.1 v2(1509.51,553.49) ; U7.2 1747.4,277.6 1790,235 C35.1 v2(1838.6,208.4) ; C36.1 v2(1840.7,873.3) ; C37.1 v2(1838.5,1069.5) ; C34.1 v2(1874.6,105.4) ; v2@1818,1256 v2(1816.35,1254.35) C38.1 v2(1876.4,1165.6) ; R24.1 v2(1870.72,440.28) 1871.51,441.06 C44.1 v2(1871.51,554.51) v2@1872,555 ; U8.2 2109.4,277.6 2151.9,235.1 C40.1 v2(2202.4,208.4) ; C41.1 v2(2202.7,873.3) v2@2203,873 ; C42.1 v2(2201.5,1069.5) v2@2202,1069 ; C39.1 v2(2238.4,105.4) ; v2@2180,1255 v2(2178.25,1253.25) C43.1 v2(2237.4,1165.6) v2@2238,1165 ; R25.1 v2(2234,440.28) 2234,494 C45.1 v2(2233.51,553) ; U4.2 2471.4,280.6 2514.1,237.9 C9.1 v2(2563.4,208.4) v2@2564,209 ; C8.1 v2(2600.6,105.4) v2@2601,105 ; R16.1 v2(2595.51,440.28) C13.1 v2(2595.51,552) ; U5.2 2833.4,277.6 2875.9,235.1 C24.1 v2(2925.6,208.4) v2@2929,205 ; C23.1 v2(2960.6,105.4) v2@2961,105 ; R19.1 v2(2958,440.28) C28.1 v2(2958,553) v2@2960,553 ; U12.2 3195.4,279.6 3237.8,237.2 C64.1 v2(3287.6,208.4) v2@3288,208 ; C67.1 v2(3286.3,873.3) v2@3287,874 ; C65.1 v2(3284.5,1069.5) v2@3286,1068 ; v2@3264,1255 v2(3264.25,1254.75) C66.1 v2(3322.6,1165.6) v2@3323,1166 ; C63.1 v2(3322,105.4) ; R37.1 v2(3320,440.28) 3320,494 C69.1 v2(3319.51,553) v2@3322,553 ; U9.2 3557.4,279.6 3600.2,236.8 C47.1 v2(3648.6,206.4) ; C48.1 v2(3648.7,873.3) v2@3650,872 ; C49.1 v2(3649.5,1069.5) v2@3652,1072 ; C46.1 v2(3685.6,105.4) v2@3687,104 ; v2@3629,1256 v2(3626.35,1253.35) C50.1 v2(3684.6,1165.6) ; R30.1 v2(3682,440.28) C56.1 v2(3682,554) v2@3685,554
  other v1: 3800,500 200,600 3900,600 100,700 3800,700 200,800 3900,800 100,900 3800,900 200,1000 3900,1000 100,1100 3800,1100 200,1200 3900,1200 100,1300 3800,1300 3900,1400 3800,1500 3200,1600 3900,1600 2900,1700 3100,1700 3300,1700 3500,1700 3800,1700 3000,1800 3200,1800 3400,1800 3600,1800 3900,1800 200,1900 400,1900 600,1900 800,1900 1000,1900 1200,1900 3100,1900 3300,1900 3500,1900 3800,1900 2734,1939 100,2000 300,2000 500,2000 700,2000 900,2000 1100,2000 1300,2000 3200,2000 3900,2000 200,2100 3800,2100 100,2200 300,2200 2800,2200 3100,2200 3300,2200 3900,2200 200,2300 2900,2300 3200,2300 3800,2300 100,2400 300,2400 2600,2400 2800,2400 3300,2400 3500,2400 3700,2400 3900,2400 200,2500 1300,2500 1500,2500 1700,2500 1900,2500 2100,2500 2900,2500 3200,2500 3400,2500 3600,2500 3800,2500 100,2600 300,2600 1200,2600 1400,2600 1600,2600 1800,2600 2000,2600 2200,2600 2600,2600 2800,2600 3300,2600 3900,2600 200,2700 1300,2700 2900,2700 3200,2700 3800,2700 100,2800 300,2800 1600,2800 1800,2800 2000,2800 2200,2800 2400,2800 2600,2800 2800,2800 3300,2800 3900,2800 200,2900 400,2900 600,2900 1000,2900 1200,2900 1700,2900 1900,2900 2100,2900 2300,2900 2500,2900 2900,2900 3200,2900 3800,2900 100,3000 300,3000 500,3000 700,3000 1100,3000 1300,3000 1600,3000 1800,3000 2000,3000 2200,3000 2400,3000 2800,3000 3000,3000 3900,3000 200,3100 400,3100 600,3100 1000,3100 1200,3100 3800,3100 3900,3200 3800,3300
I2C_A0: J2.4 R7.1 U3.29 | length 1014.6
  Top Layer w4: J2.4 1714,1942 ; R7.1 1714,1942 ; U3.29 2430,2051 ccw(c2403.44,2051) 2422.22,2069.78 2407.61,2084.39 ccw(c2372.34,2049.12) 2372.34,2099 2270.42,2099 ccw(c2270.42,1999) 2199.71,2069.71 2101.29,1971.29 cw(c2030.58,2042) 2030.58,1942 1714,1942
I2C_RSTN: J2.2 R6.1 U3.26 | length 1177.5
  Top Layer w4: R6.1 v1(1770,1910.1) ; v1(2421.22,2142) cw(c2421.22,2109.22) 2454,2109.22 U3.26
  Bottom Layer w4: J2.2 1770,2042 ; v1(1770,1910.1) 1770,2042 ; v1(2421.22,2142) 2209,2142 2109,2042 1770,2042
I2C_SCL: R4.1 U1.3 U3.28 | length 1214.9
  Top Layer w4: 2096,2384.6 cw(c2096,2316.02) 2144.49,2364.51 2432.24,2076.76 ; 2431.5,2077.46 2432.23,2076.74 ; U3.28 2438,2061.81 ccw(c2415.81,2061.81) 2432.23,2076.74
  Top Layer w6: U1.3@1505.04,2384.6 2096,2384.6 ; R4.1 1625.3,2384.5
I2C_SDA: R5.1 U1.4 U3.27 | length 1263.2
  Top Layer w4: 2060,2410.19 2076.39,2410.19 cw(c2076.39,2310.19) 2147.1,2380.9 2439,2089 cw(c2422.1,2072.1) 2446,2072.1 U3.27
  Top Layer w6: U1.4@1505.04,2410.19 2060,2410.19 ; R5.1 v1(1670,2327.4)
  Bottom Layer w6: v1(1670,2327.4) v1(1670,2410.2)
NetC1_1: C1.1 J3.1 R11.2 | length 1693.8
  Top Layer w5: J3.1 1429.28,1628.1 ccw(c1429.28,1728.1) 1499.99,1657.39 1579.71,1737.11 cw(c1650.42,1666.4) 1650.42,1766.4 R11.2 C1.1
NetC1_2: C1.2 R8.1 R12.2 U3.1 | length 575.8
  Top Layer w4: C1.2 C1.2@2007.71,1766.41 ; R12.2 R8.1 ; 2456.97,1900.97 ccw(c2425.41,1932.47) 2470,1932.47 U3.1
  Top Layer w5: C1.2@2007.71,1766.41 R8.1 2091.99,1766.41 ccw(c2091.99,1866.41) 2162.7,1795.7 2227.71,1860.71 cw(c2298.42,1790) 2298.42,1890 2430.44,1890 ccw(c2430.44,1927.56) 2456.97,1900.97
NetC4_2: C4.2 L1.1 P1.2 | length 234.3
  Top Layer w15: P1.2@1348,698 P1.2 C4.2 L1.1
NetC7_2: C7.2 R10.1 | length 41.5
  Top Layer w10: R10.1 C7.2
NetC10_2: C10.2 L2.1 P2.2 | length 214.3
  Top Layer w15: P2.2 C10.2 L2.1
NetC13_2: C13.2 R15.1 | length 41.5
  Top Layer w10: R15.1 C13.2
NetC14_1: C14.1 J10.1 | length 212.6
  Top Layer w6: C14.1 J10.1@2939.4,3314
  Top Layer w10: J10.1@2939.4,3314 J10.1
NetC15_1: C15.1 J11.1 | length 220.4
  Top Layer w6: J11.1 C15.1@2559.9,3313.9
NetC25_2: C25.2 L3.1 P3.2 | length 214.3
  Top Layer w15: P3.2 C25.2 L3.1
NetC28_2: C28.2 R18.1 | length 42
  Top Layer w10: R18.1 C28.2
NetC36_2: C36.2 L4.1 P4.2 | length 214.3
  Top Layer w15: P4.2 L4.1
NetC41_2: C41.2 L5.1 P5.2 | length 277
  Top Layer w10: C41.2 L5.1
  Top Layer w15: P5.2 L5.1@2072,936
NetC44_2: C44.2 R21.1 | length 41.5
  Top Layer w15: R21.1 C44.2
NetC45_2: C45.2 R23.1 | length 41.5
  Top Layer w15: R23.1 C45.2
NetC48_2: C48.2 L6.1 P6.2 | length 198.3
  Top Layer w15: P6.2 C48.2@3520,857.3 ; C48.2 L6.1
NetC53_2: C53.2 L7.1 P7.2 | length 222.3
  Top Layer w15: P7.2 L7.1
NetC56_2: C56.2 R27.1 | length 42
  Top Layer w10: R27.1 C56.2
NetC57_2: C57.2 R29.1 | length 42.1
  Top Layer w10: R29.1 C57.2
NetC60_2: C60.2 L8.1 P8.2 | length 214.3
  Top Layer w15: P8.2 L8.1
NetC67_2: C67.2 L9.1 P9.2 | length 198.3
  Top Layer w15: P9.2 C67.2@3158,857.3 ; C67.2 L9.1
NetC68_2: C68.2 R33.1 | length 42
  Top Layer w15: R33.1 C68.2
NetC69_2: C69.2 R35.1 | length 41.5
  Top Layer w10: R35.1 C69.2
NetJ1_2: J1.2 R1.1 U1.5 | length 620.4
  Top Layer w6: J1.2 956.2,2345.2 956.2,2409.1 979.7,2432.6 1135.9,2432.6 1158.31,2410.19 U1.5@1272.76,2410.19 ; R1.1 v1(1194.8,2330)
  Bottom Layer w6: v1(1194.8,2330) v1(1194.8,2410.2)
  other v1: 1194.8,2410.2
NetJ1_3: J1.3 R2.1 U1.6 | length 621.2
  Top Layer w4: J1.3 1150,2384.6
  Top Layer w6: J1.3 1017.41,2385.21 1272.14,2385.21 1271.53,2384.6 1150,2384.6 R2.1
NetP1_1: P1.1 R9.2 R10.2 U2.5 | length 225.4
  Top Layer w15: U2.5 R9.2 R10.2 P1.1
NetP2_1: P2.1 R14.2 R15.2 U4.5 | length 225.4
  Top Layer w15: U4.5 P2.1
NetP3_1: P3.1 R17.2 R18.2 U5.5 | length 279.1
  Top Layer w10: R17.2 R18.2
  Top Layer w15: U5.5 P3.1
NetP4_1: P4.1 R20.2 R21.2 U7.5 | length 225.4
  Top Layer w15: U7.5 P4.1
NetP5_1: P5.1 R22.2 R23.2 U8.5 | length 225.4
  Top Layer w15: U8.5 R22.2 ; R22.2 R23.2 P5.1
NetP6_1: P6.1 R26.2 R27.2 U9.5 | length 225.4
  Top Layer w15: U9.5 P6.1
NetP7_1: P7.1 R28.2 R29.2 U10.5 | length 217.2
  Top Layer w10: P7.1@623.9,609.9 P7.1@624,590
  Top Layer w15: 623.9,412.64 P7.1@623.9,609.9
NetP8_1: P8.1 R32.2 R33.2 U11.5 | length 279.1
  Top Layer w10: R32.2 R33.2
  Top Layer w15: U11.5 P8.1
NetP9_1: P9.1 R34.2 R35.2 U12.5 | length 225.4
  Top Layer w15: U12.5 P9.1
NetR3_1: R3.1 U1.7 U1.8 | length 82.8
  Top Layer w6: U1.8@1272.76,2333.41 U1.7@1272.76,2359 ; R3.1 U1.8@1273,2332.17
NetR9_1: R9.1 R13.2 U2.4 | length 86.5
  Top Layer w10: R9.1 R13.2 1426.01,423.27 cw(c1415.73,423.27) 1423,416 1422.8,415.8 U2.4
NetR14_1: R14.1 R16.2 U4.4 | length 86.5
  Top Layer w10: R14.1 R16.2 2512.01,423.85 cw(c2505.15,423.85) 2510,419 ccw(c2512.89,416.11) 2508.8,416.11 U4.4
NetR17_1: R17.1 R19.2 U5.4 | length 86.5
  Top Layer w10: R17.1 R19.2 2874.01,426.27 cw(c2863.73,426.27) 2871,419 2870.8,418.8 U5.4
NetR20_1: R20.1 R24.2 U7.4 | length 86.5
  Top Layer w15: R20.1 R24.2 1788.01,421.85 cw(c1781.15,421.85) 1786,417 ccw(c1788.89,414.11) 1784.8,414.11 U7.4
NetR22_1: R22.1 R25.2 U8.4 | length 86.5
  Top Layer w15: R22.1 R25.2 2150.01,421.85 cw(c2143.15,421.85) 2148,417 2148,395.54 cw(c2143.91,395.54) U8.4
NetR26_1: R26.1 R30.2 U9.4 | length 86.5
  Top Layer w10: R26.1 R30.2 3598.01,422.85 cw(c3591.15,422.85) 3596,418 ccw(c3598.89,415.11) 3594.8,415.11 U9.4
NetR28_1: R28.1 R31.2 U10.4 | length 87.4
  Top Layer w10: R28.1 R31.2 701.91,418.71 cw(c698.8,418.71) 698.8,415.6 U10.4
NetR32_1: R32.1 R36.2 U11.4 | length 86.5
  Top Layer w15: R32.1 R36.2 1064.01,422.85 cw(c1057.15,422.85) 1062,418 ccw(c1064.89,415.11) 1060.8,415.11 U11.4
NetR34_1: R34.1 R37.2 U12.4 | length 86.5
  Top Layer w10: R34.1 R37.2 3236.01,420.85 cw(c3229.15,420.85) 3234,416 ccw(c3236.89,413.11) 3232.8,413.11 U12.4
OUT_TS: J4.1 U3.6 | length 1178.2
  Top Layer w4: U3.6 2553.35,1949 cw(c2553.35,1897.45) 2557.14,1948.86 cw(c2553.35,1897.45) 2589.8,1933.9
  Top Layer w5: 2589.8,1933.9 2980.51,1543.19 ccw(c3051.22,1613.9) 3051.22,1513.9 J4.1
PULSE_IN_N: J6.1 U3.19 | length 2421.1
  Top Layer w4: J6.1 1371.94,3313.9 cw(c1371.94,3253.12) 1432.72,3253.12 1432.72,2842.1 ccw(c1543.72,2842.1) 1465.23,2763.61 1523.32,2705.52 ccw(c1578.66,2760.86) 1578.66,2682.6 2267.98,2682.6 cw(c2267.98,2582.6) 2338.69,2653.31 2455.01,2536.99 cw(c2384.3,2466.28) 2484.3,2466.28 2484.3,2188.9 2486,2181 U3.19
PULSE_IN_P: J8.1 U3.18 | length 2423.6
  Top Layer w4: J8.1 1504.5,3313.9 ccw(c1504.5,3253.12) 1443.72,3253.12 1443.72,2842.1 ccw(c1543.72,2842.1) 1473.01,2771.39 1531.1,2713.3 ccw(c1578.66,2760.86) 1578.66,2693.6 2267.98,2693.6 cw(c2267.98,2582.6) 2346.47,2661.09 2462.79,2544.77 cw(c2384.3,2466.28) 2495.3,2466.28 2495.3,2188.9 2494,2180.6 U3.18
TESTOUT_TS: J5.1 U3.9 | length 1099.4
  Top Layer w4: U3.9 2555.62,1973 cw(c2555.62,1928.62) 2587,1960 ; J5.1@3539.1,2113.5 J5.1
  Top Layer w5: 2587,1960 2618.3,1928.7 ccw(c2655,1965.41) 2655,1913.5 2907.08,1913.5 ccw(c2907.08,2013.5) 2977.79,1942.79 3119.21,2084.21 cw(c3189.92,2013.5) 3189.92,2113.5 J5.1@3539.1,2113.5
VDD2V5: C5.2 C6.2 C30.2 L1.2 U3.4 | length 781.9
  Top Layer w4: v1(2348,1620) C30.2 ; v1(2348,1680) C30.2 ; U3.4 2494,1830.7 cw(c2278.4,1830.7) 2431,1678.39 2422.82,1670.22 cw(c2374,1719.05) 2374,1650 C30.2
  Top Layer w15: v2(1288.4,1165.6) C6.2 v2(1347.95,1253.95) ; v2(1297.5,1069.5) C5.2 ; L1.2 C5.2 ; C6.2@1348,1165.55 C5.2
VDD_5V: C2.2 C3.2 C8.2 C9.2 C23.2 C24.2 C32.2 C33.2 C34.2 C35.2 C39.2 C40.2 C46.2 C47.2 C51.2 C52.2 C58.2 C59.2 C63.2 C64.2 J12.1 U2.1 U2.3 U4.1 U4.3 U5.1 U5.3 U6.3 U7.1 U7.3 U8.1 U8.3 U9.1 U9.3 U10.1 U10.3 U11.1 U11.3 U12.1 U12.3 | length 3723.3
  Top Layer w8: U12.1 3158,325 3169,336 3222,336 3232.8,325.2 U12.3
  Top Layer w10: U10.1 624,324.1 635.8,335.9 685.5,335.9 698.8,322.6 U10.3 ; C51.2 U10.1@624.05,298.16 ; U11.1 986,326 998,338 1048,338 1060.8,325.2 U11.3 ; U2.1@1348.05,298.1 U2.1 1348,324 1360,336 1410,336 1422.8,323.2 U2.3 ; U7.1 1710,327.68 1722.32,340 1772,340 1784.8,327.2 U7.3 ; U8.1 2072,325 2083,336 2138,336 2146.8,327.2 U8.3 ; U4.1 2434,327 2444,337 2498,337 2508.8,326.2 U4.3 ; U5.1 2796,324 2807,335 2860,335 2870.8,324.2 U5.3 ; U9.1 3520,326 3531,337 3585,337 3594.8,327.2 U9.3
  Top Layer w15: U6.3 414.4,795.6 540,670 540,360 525.8,345.8 C33.2 ; C52.2 U10.1@623.9,298.06 ; C58.2 U11.1@985.95,298.11 ; C2.2 U2.1@1348.05,298.1 ; C35.2 U7.1 ; C34.2 C35.2@1710.05,208.35 ; C39.2 U8.1@2071.95,298.11 ; C8.2 U4.1@2434.05,298.1 ; C23.2 U5.1@2795.95,298.11 ; C63.2 U12.1@3157.95,298.11 ; U9.1 3520.15,298 C46.2
  other v1: 350,100 450,100 550,100 900,100 1275,100 1625,100 2000,100 2375,100 2725,100 3075,100 3450,100 350,150 450,150 550,150 900,150 1275,150 1625,150 2000,150 2375,150 2725,150 3075,150 3450,150 350,200 450,200 550,200 900,200 1275,200 1625,200 2000,200 2375,200 2725,200 3075,200 3450,200 350,250 450,250
VDD_DMRO: C17.2 C42.2 C43.2 L5.2 U3.11 | length 526.8
  Top Layer w4: U3.11 2563,1989 cw(c2563,1938.3) 2598.83,1974.17 2621.98,1951.02 ccw(c2651,1980.04) 2651,1939 C17.2
  Top Layer w6: C17.2 v1(2665,1970)
  Top Layer w15: v2@2013,1166 v2(2013.45,1165.55) 2072,1165.55 C42.2 ; v2@2024,1070 v2(2024.5,1069.5) C42.2 ; C43.2 v2(2071.95,1253.95) v2(2071.95,1253.95) ; L5.2 C42.2
VDD_EFUSE: C29.2 C61.2 C62.2 L8.2 R8.2 U3.2 | length 685
  Top Layer w4: C29.2@2349.6,1814.7 2387,1814.7 ccw(c2387,1869.5) 2425.75,1830.75 2470.3,1875.3 ccw(c2451.71,1893.89) 2478,1893.89 U3.2
  Top Layer w6: C29.2@2349.6,1814.7 v1(2349.6,1848.5) ; v1(2350,1781.2) C29.2
  Top Layer w8: v2@2062,1851 v2(2062,1855) 2062,1806.61 R8.2
  Top Layer w10: C62.2@986,1165.55 C62.2
  Top Layer w15: v2(927,1165.6) C62.2 v2(986.05,1255) v2@988,1255 ; v2@935,1069 v2(935,1069.5) C61.2 ; L8.2 C61.2 ; C62.2@986,1165.55 C61.2
VDD_ERX: C20.2 C26.2 C27.2 L3.2 U3.20 | length 668
  Top Layer w4: C20.2 2460,2202.86 ccw(c2490.25,2202.86) 2468.86,2181.46 cw(c2446.8,2159.4) 2478,2159.4 U3.20
  Top Layer w6: v1(2427,2309) C20.2
  Top Layer w15: v2@2737,1164 v2(2738.6,1165.6) C27.2 v2(2795.95,1252.05) v2@2795,1253 ; v2(2749.5,1069.5) C26.2 ; L3.2 C26.2 ; C27.2@2796,1165.55 C26.2
VDD_I2C: C22.2 C54.2 C55.2 L7.2 R4.2 R5.2 R6.2 R7.2 U1.2 U3.30 | length 682.1
  Top Layer w4: C22.2 2372,2027 C22.2@2371,2028 ; C22.2@2376,2026 U3.30
  Top Layer w6: R4.2 R5.2 1670.6,2234 1671.6,2235 v1(1716,2235) ; v1(1670,1829.9) R7.2 ; R6.2 1770.2,1830.1 v1(1810,1830.1) ; C22.2@2371,2028 v1(2371,2064)
  Top Layer w10: U1.2@1505.04,2359 1561,2359 v1(1577,2343)
  Top Layer w15: v2(567,1166) 623.45,1166 C55.2 v2(623.85,1251) ; v2(577,1068) 622.4,1068 C54.2 ; L7.2 C54.2 ; C55.2@623.9,1165.55 C54.2
VDD_IO: C21.2 C49.2 C50.2 L6.2 U3.25 | length 735.8
  Top Layer w4: C21.2 2302,2295.87 2448.66,2149.22 cw(c2416.44,2117) 2462,2117 U3.25
  Top Layer w6: v1(2265,2309) C21.2
  Top Layer w15: v2@3461,1166 v2(3461.45,1165.55) 3520,1165.55 C49.2 ; v2@3470,1069 v2(3470.5,1069.5) C49.2 ; L6.2 C49.2 ; C50.2 v2(3520.05,1253.05) v2@3521,1254
VDD_TDC_ANAL: C18.2 C65.2 C66.2 L9.2 U3.22 | length 698.6
  Top Layer w4: C18.2 2384,2284 ccw(c2456.43,2284) 2405.21,2232.79 2448.08,2189.92 cw(c2395.16,2137) 2469.7,2143.65 2469.7,2137.3 ; U3.22 2470,2137.3
  Top Layer w6: v1(2351,2309) C18.2
  Top Layer w15: v2@3099,1166 v2(3099.4,1165.6) C66.2 v2(3157.95,1255.05) v2@3157,1256 ; v2@3108,1069 v2(3108.5,1069.5) C65.2 ; L9.2 C65.2 ; C66.2@3158,1165.55 C65.2
VDD_TDC_DIG: C11.2 C12.2 C19.2 L2.2 U3.16 | length 498.5
  Top Layer w4: U3.16 2502,2078.44 cw(c2539.56,2078.44) 2512.97,2104.97 ; 2513.03,2105.03 cw(c2539.56,2078.44) 2539.56,2116 C19.2 v1(2556,2146)
  Top Layer w10: C11.2 C12.2@2434,1165.55
  Top Layer w15: v2(2375.4,1165.6) C12.2 v2(2433.95,1251.95) ; v2(2391.5,1069.5) C11.2 L2.2
VDD_TS: C16.2 C37.2 C38.2 L4.2 U3.7 | length 555.6
  Top Layer w4: U3.7 2523,1957 2518,1952 2518,1929 ccw(c2561.46,1929) 2530.73,1898.27 2532.03,1896.97 cw(c2491.06,1856) 2549,1856 C16.2
  Top Layer w6: v1(2549,1781) C16.2
  Top Layer w15: v2@1650,1166 v2(1650.4,1165.6) C38.2 v2(1710.05,1254.05) v2@1714,1258 ; v2(1660.5,1069.5) C37.2 ; L4.2 C37.2 ; C38.2@1710,1165.55 C37.2
VEXT: J1.1 R1.2 R2.2 R3.2 | length 277.1
  Top Layer w6: J1.1 1068.4,2184.6 1118.4,2234.6 R2.2 1150.4,2235 R1.2 R3.2
VREF_TS: C31.2 U3.5 U6.4 | length 2821.7
  Top Layer w4: C31.2 414.4,1281.98 cw(c514.4,1281.98) 443.69,1352.69 533.71,1442.71 cw(c604.42,1372) 604.42,1472 2273.58,1472 ccw(c2273.58,1572) 2344.29,1501.29 2472.71,1629.71 ccw(c2402,1700.42) 2502,1700.42 U3.5
  Top Layer w15: U6.4 C31.2
pads on no net: J1. J1.4 J1.5 U3.0@2435.12,1996.8 U3.0@2438.66,1996.8 U3.0@2442.4,1996.8 U3.0@2446.73,1996.8 U3.0@2451.06,1996.8 U3.0@2455.4,1996.8 U3.0@2459.14,1996.8 U3.0@2462.68,1996.8 U3.0@2466.2,1996.8 U3.0@2470.53,1996.8 U3.0@2473.76,1996.8 U3.0@2476.03,1962.57 U3.0@2478.19,1996.8 U3.0@2479.13,1962.57 U3.0@2481.37,1996.8 U3.0@2482.13,1962.57 U3.0@2485.71,1996.8 U3.0@2489.52,1996.8 U3.0@2492.94,1962.57 U3.0@2493.07,1996.8 U3.0@2496.89,1996.77 U3.0@2499.92,1962.57 U3.0@2501.22,1996.8 U3.0@2506.17,1965.18 U3.0@2506.17,1969.11 U3.0@2506.17,1972.11 U3.0@2506.17,1976.05 U3.0@2506.17,1979.89 U3.0@2506.17,1982.89 U3.0@2506.17,1986.07 U3.0@2506.17,1990.01 U6.1 U6.6

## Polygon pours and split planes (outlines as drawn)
GND on Bottom Layer "Signal-No Net" (solid, pour order 2): 0,0 4000,0 4000,1700 4000,3600 0,3600
no net on Bottom Layer "Signal-No Net" (solid, pour order 4): 0,0 4000,0 4000,3600 0,3600 0,0
GND on Top Layer "Signal-No Net" (solid, pour order 6): 0,0 4000,0 4000,3600 0,3600 0,0
GND on GND (split plane): 3979.9,20.1 20.1,20.1 20.1,3579.9 3979.9,3579.9
VDD_TDC_DIG on POWER (split plane): 2972.44,2116.87 2972.44,1533.13 2654.65,1215.35 2653.45,1213.78 2653.14,1213.03 2652.69,1211.96 2652.44,1210 2652.44,401.56 2298.56,401.56 2298.56,1227.87 2377.13,1306.44 2548,1306.44 2549.96,1306.69 2551.03,1307.14 2551.78,1307.45 2553.35,1308.65 2828.35,1583.65 2829.55,1585.22 2830.31,1587.04 2830.56,1589 2830.56,1993 2830.31,1994.96 2829.86,1996.03 2829.55,1996.78 2828.35,1998.35 2785.35,2041.35 2783.78,2042.55 2783.03,2042.86 2781.96,2043.31 2780,2043.56 2634,2043.56 2632.04,2043.31 2630.22,2042.55 2628.65,2041.35 2571.47,1984.16 2470.16,1984.16 2470.16,2180.23 2470.72,2180.65 2540.7,2250.64 2838.67,2250.64
VDD_DMRO on POWER (split plane): 2815.44,1989.87 2815.44,1592.13 2544.87,1321.56 2374,1321.56 2372.04,1321.31 2370.22,1320.55 2368.65,1319.35 2285.65,1236.35 2284.45,1234.78 2284.14,1234.03 2283.69,1232.96 2283.44,1231 2283.44,401.56 1936.56,401.56 1936.56,1305.87 2061.13,1430.44 2477,1430.44 2478.96,1430.69 2480.03,1431.14 2480.78,1431.45 2482.35,1432.65 2667.35,1617.65 2668.55,1619.22 2669.31,1621.04 2669.56,1623 2669.56,1847 2669.31,1848.96 2668.55,1850.78 2667.35,1852.35 2631.35,1888.35 2629.78,1889.55 2629.03,1889.86 2627.96,1890.31 2626,1890.56 2470.16,1890.56 2470.16,1969.04 2574.6,1969.04 2576.56,1969.29 2577.63,1969.74 2578.38,1970.05 2579.95,1971.25 2637.13,2028.44 2776.87,2028.44
VDD_TS on POWER (split plane): 2654.44,1843.87 2654.44,1626.13 2473.87,1445.56 2058,1445.56 2056.04,1445.31 2054.22,1444.55 2052.65,1443.35 1923.65,1314.35 1922.45,1312.78 1922.14,1312.03 1921.69,1310.96 1921.44,1309 1921.44,401.56 1575.96,401.56 1575.96,1330.47 1795.93,1550.44 2382.9,1550.44 2384.86,1550.69 2385.93,1551.14 2386.68,1551.45 2388.25,1552.65 2467.95,1632.35 2469.15,1633.92 2469.91,1635.74 2470.16,1637.7 2470.16,1802.6 2470.16,1875.44 2622.87,1875.44
VDD_TDC_ANAL on POWER (split plane): 3383.44,2405.87 3383.44,401.56 3029.56,401.56 3029.56,1311.87 3141.35,1423.65 3142.55,1425.22 3143.31,1427.04 3143.56,1429 3143.56,2354 3143.31,2355.96 3142.86,2357.03 3142.55,2357.78 3141.35,2359.35 2995.35,2505.35 2993.78,2506.55 2993.03,2506.86 2991.96,2507.31 2990,2507.56 2499,2507.56 2497.04,2507.31 2495.22,2506.55 2493.65,2505.35 2385.65,2397.35 2384.45,2395.78 2384.14,2395.03 2383.69,2393.96 2383.44,2392 2383.44,2193.56 2311.56,2193.56 2311.56,2575.87 2415.13,2679.44 3109.87,2679.44
VDD_ERX on POWER (split plane): 3128.44,2350.87 3128.44,1432.13 3016.65,1320.35 3015.45,1318.78 3015.14,1318.03 3014.69,1316.96 3014.44,1315 3014.44,401.56 2667.56,401.56 2667.56,1206.87 2985.35,1524.65 2986.55,1526.22 2987.31,1528.04 2987.56,1530 2987.56,2120 2987.31,2121.96 2986.55,2123.78 2985.35,2125.35 2847.15,2263.55 2845.58,2264.75 2844.83,2265.06 2843.76,2265.51 2841.8,2265.76 2537.57,2265.76 2535.61,2265.51 2533.79,2264.75 2532.22,2263.55 2462.24,2193.56 2398.56,2193.56 2398.56,2388.87 2502.13,2492.44 2986.87,2492.44
VDD_IO on POWER (split plane): 3979.9,401.56 3398.56,401.56 3398.56,2409 3398.31,2410.96 3397.86,2412.03 3397.55,2412.78 3396.35,2414.35 3118.35,2692.35 3116.78,2693.55 3116.03,2693.86 3114.96,2694.31 3113,2694.56 2412,2694.56 2410.04,2694.31 2408.22,2693.55 2406.65,2692.35 2298.65,2584.35 2297.45,2582.78 2297.14,2582.03 2296.69,2580.96 2296.44,2579 2296.44,2193.56 2089.13,2193.56 2087.35,2195.35 1452.35,2830.35 1450.78,2831.55 1450.03,2831.86 1448.96,2832.31 1447,2832.56 20.1,2832.56 20.1,3579.9 3979.9,3579.9
VDD2V5 on POWER (split plane): 2455.04,1640.83 2379.77,1565.56 1792.8,1565.56 1790.84,1565.31 1789.02,1564.55 1787.45,1563.35 1563.05,1338.95 1561.85,1337.38 1561.54,1336.63 1561.09,1335.56 1560.84,1333.6 1560.84,401.56 1207.56,401.56 1207.56,1478.87 1399.13,1670.44 2179,1670.44 2180.96,1670.69 2182.03,1671.14 2182.78,1671.45 2184.35,1672.65 2242.13,1730.44 2455.04,1730.44
VDD_EFUSE on POWER (split plane): 2455.04,1802.6 2455.04,1745.56 2239,1745.56 2237.27,1745.34 2237.04,1745.31 2235.22,1744.55 2233.65,1743.35 2175.87,1685.56 1396,1685.56 1394.04,1685.31 1392.22,1684.55 1390.65,1683.35 1194.65,1487.35 1193.45,1485.78 1193.14,1485.03 1192.69,1483.96 1192.44,1482 1192.44,401.56 844.56,401.56 844.56,1653.87 985.13,1794.44 1902,1794.44 1903.96,1794.69 1905.03,1795.14 1905.78,1795.45 1907.35,1796.65 2039.13,1928.44 2455.04,1928.44
VDD_5V on POWER (split plane): 3979.9,20.1 20.1,20.1 20.1,386.44 3979.9,386.44
VDD_I2C on POWER (split plane): 2076.65,2184.65 2080.65,2180.65 2082.22,2179.45 2084.04,2178.69 2086,2178.44 2455.04,2178.44 2455.04,1976.6 2455.04,1943.56 2036,1943.56 2034.27,1943.34 2034.04,1943.31 2032.22,1942.55 2030.65,1941.35 1898.87,1809.56 982,1809.56 980.04,1809.31 978.97,1808.86 978.22,1808.55 976.65,1807.35 831.65,1662.35 830.45,1660.78 830.14,1660.03 829.69,1658.96 829.44,1657 829.44,401.56 20.1,401.56 20.1,2817.44 1443.87,2817.44

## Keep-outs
Keep-Out Layer:
  the board outline again, w10
  text "Keep-Out Layer" at 4145,1147 h50

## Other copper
Top Layer:
  rectangle net VDD_5V: 16,278 320,390
  rectangle net VDD_5V: 300,40 525,390
  rectangle net VDD_5V: 510,40 650,240
  rectangle net VDD_5V: 870,40 1010,240
  rectangle net VDD_5V: 1231.6,41.1 1371.6,241.1
  rectangle net VDD_5V: 1591.6,42.1 1731.6,242.1
  rectangle net VDD_5V: 1961.6,42.1 2101.6,242.1
  rectangle net VDD_5V: 2321.6,42.1 2461.6,242.1
  rectangle net VDD_5V: 2681.6,42.1 2821.6,242.1
  rectangle net VDD_5V: 3041.6,42.1 3181.6,242.1
  rectangle net VDD_5V: 3401.6,42.1 3541.6,242.1
  text "ET2 Test Board" at 321,3464 h60
  text "2021/11/24" at 316,3376 h60
  text "Designed By: Wei Zhang" at 316,3297 h60
  text "Top Layer" at 4145,2563 h50
Bottom Layer:
  text "Bottom Layer" at 4145,2139 h50
GND (plane layer: these items are gaps in the copper):
  text "GND Layer" at 4145,2422 h50
POWER (plane layer: these items are gaps in the copper):
  lines w15: -4,2825 1447,2825 2082,2190 2086,2186 2465.37,2186 2537.57,2258.2 2841.8,2258.2 2980,2120 2980,1530 2660,1210 2660,394 ; 3,394 4000,394 ; 837,394 837,1657 982,1802 1902,1802 2036,1936 2462.6,1936 2462.6,2186 ; 1200,394 1200,1482 1396,1678 2179,1678 2239,1738 2462.6,1738 ; 1568.4,394 1568.4,1333.6 1792.8,1558 2382.9,1558 2462.6,1637.7 2462.6,1802.6 2462.6,1976.6 2574.6,1976.6 2634,2036 2780,2036 2823,1993 2823,1589 2548,1314 2374,1314 2291,1231 2291,394 ; 1929,394 1929,1309 2058,1438 2477,1438 2662,1623 2662,1847 2626,1883 2462.6,1883 ; 2304,2186 2304,2579 2412,2687 3113,2687 3391,2409 3391,394 ; 2391,2186 2391,2392 2499,2500 2990,2500 3136,2354 3136,1429 3022,1315 3022,394
  text "Power Layer" at 4145,2280 h50

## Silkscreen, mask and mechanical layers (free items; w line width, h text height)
Top Overlay:
  lines w10: 770,3010 730,3010 710,2990 710,2460 740,2430 910,2430 ; 800,2810 770,2840 770,3160 800,3190 ; 950,2150 910,2190 910,2680 950,2720
  text "Pulse" at 1337,3492 h50
  text "Clk1G28" at 2481,3492 h50
  text "N" at 1358,3237 h50 r180
  text "N" at 2557,3237 h50 r180
  text "P" at 1523,3187.02 h50
  text "P" at 2722,3187.02 h50
  text "Dataout" at 3729,3163 h50 r270
  text "GND" at 810,3140 h40
  text "P" at 3465,3100 h50 r90
  text "NA" at 810,3077 h40
  text "NA" at 810,3012 h40
  text "SCL" at 810,2947 h40
  text "N" at 3415,2935 h50 r270
  text "SDA" at 810,2884 h40
  text "Vext" at 810,2820 h40
  text "Testout_TS" at 3737.33,2359 h50 r270
  text "Top Overlay" at 4145,1997 h50
  text "Ext_Clk(8M)" at 88,1874 h50 r270
  text "Out_TS" at 3737.33,1649 h50 r270
  text "Vdd_I2C" at 567,1323 h35
  text "Vdd_eFuse" at 889,1323 h35
  text "Vdd2V5" at 1308,1323 h35
  text "Vdd_TS" at 1668,1323 h35
  text "Vdd_DMRO" at 1996,1323 h35
  text "Vdd_TDC_Dig" at 2305,1323 h35
  text "Vdd_eRx" at 2735,1323 h35
  text "Vdd_TDC_Anal" at 3014,1323 h35
  text "Vdd_IO" at 3700,1231 h35
Bottom Overlay:
  text "Bottom Overlay" at 4145,1855 h50
Top Paste:
  text "Top Paste" at 4145,1714 h50
Bottom Paste:
  text "Bottom Paste" at 4145,1555 h50
Top Solder:
  rectangle: 315.52,3457.57 693.52,3505.57
  text "Top Solder" at 4145,1430 h50
Bottom Solder:
  text "Bottom Solder" at 4145,1272 h50
Mechanical 1:
  text "Mechanical 1" at 4145,989 h50
Mechanical 5:
  text "Mechanical 5" at 4137,839 h50
Mechanical 13:
  text "Mechanical 13" at 4145,706 h50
